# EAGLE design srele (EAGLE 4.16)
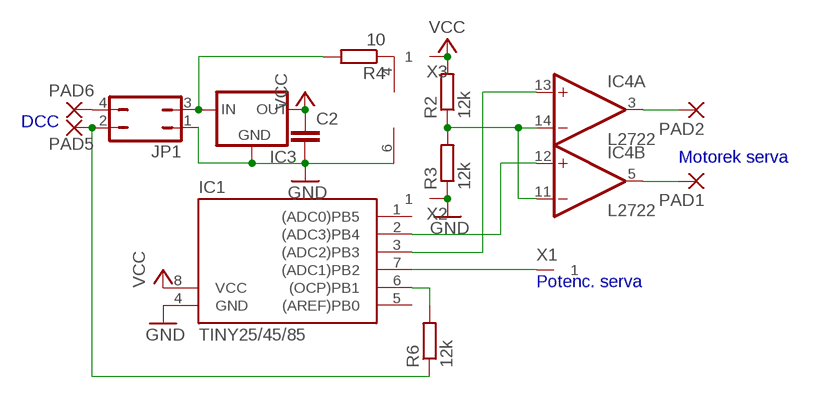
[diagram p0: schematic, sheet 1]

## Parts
C2  C-EU025-024X044  [C025-024X044]
IC1  TINY25/45/85  TINY15LP  [DIL08]
IC3  78LXX  [78LXX]
IC4  L2722  [SO16]
JP1  JP2Q  [JP2Q]
PAD1  SMD5  [SMD5]
PAD2  SMD5  [SMD5]
PAD5  SMD2  [SMD2]
PAD6  SMD2  [SMD2]
R2  12k  R-EU_0204/5  [0204/5]
R3  12k  R-EU_0204/5  [0204/5]
R4  10  R-EU_0207/10  [0207/10]
R6  12k  R-EU_0204/5  [0204/5]
X1  PAD-Y-ASYM  [Y_LONG_ASYM]
X2  PAD-Y-ASYM  [Y_LONG_ASYM]
X3  PAD-Y-ASYM  [Y_LONG_ASYM]

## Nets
GND: C2.2 IC1.4(GND) IC3.GND IC4.6(P:GND) JP1.1 R3.1 X2.A1
N$1: IC4.11(B:-IN) IC4.14(A:-IN) R2.1 R3.2
N$2: IC1.3((ADC2)PB3) IC4.13(A:+IN)
N$3: IC1.6((OCP)PB1) R6.2
N$4: IC1.2((ADC3)PB4) IC4.12(B:+IN)
N$5: JP1.2 PAD5.1(P) R6.1
N$6: IC4.3(A:OUT) PAD2.1(P)
N$8: IC4.5(B:OUT) PAD1.1(P)
N$9: IC4.4(P:V+) R4.1
N$10: JP1.4 PAD6.1(P)
N$12: IC1.7((ADC1)PB2) X1.A1
N$16: IC3.IN JP1.3 R4.2
VCC: C2.1 IC1.8(VCC) IC3.OUT R2.2 X3.A1
Unconnected: IC1.1((ADC0)PB5) IC1.5((AREF)PB0)

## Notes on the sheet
- DCC
- Motorek serva
- Potenc. serva

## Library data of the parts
C2 = RCL:C-EU: CAPACITOR, European symbol
IC1 = atmel-1:TINY15L: MICROCONTROLLER 2.7 V 1 Kbytes FLASH 64 bytes EEPROM 4-channel 10 bit ADC
IC3 = v-reg:78LXX: VOLTAGE REGULATOR
IC4 = LINEAR:L2722: OP AMP
JP1 = JUMPER:JP2Q: JUMPER
PAD1 PAD2 = wirepad:SMD5: SMD PAD
PAD5 PAD6 = wirepad:SMD2: SMD PAD
R2-R4 R6 = RCL:R-EU_: RESISTOR, European symbol
X1-X3 = special-pad:PAD-Y-ASYM: Y Long asymetrical Pad

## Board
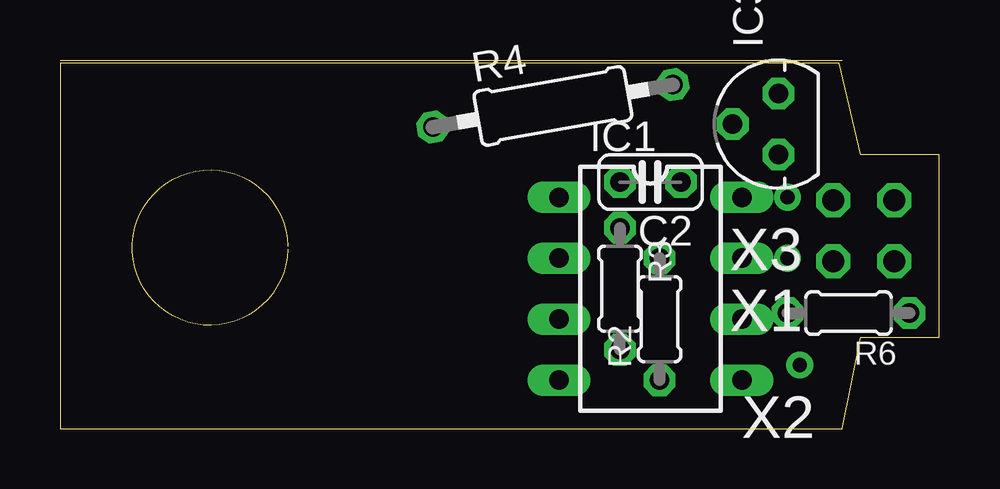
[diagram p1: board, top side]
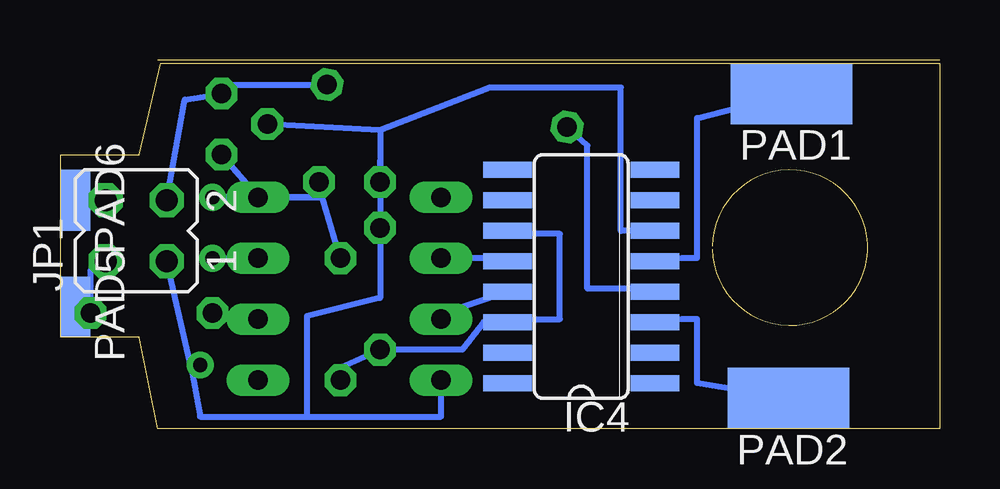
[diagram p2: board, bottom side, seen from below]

Size 36.63 x 15.37 mm. Coordinates in mm from the lower left corner, seen from the top.
Outline: 9.49,7.49 arc-358 9.49,7.62
Outline: 0,15.37 32.6,15.37
Outline: 36.63,11.42 33.36,11.42 32.47,15.24 0,15.23 0,0.01 32.6,0 33.36,3.82 36.63,3.82 36.63,11.42
Copper layers (1*16): Top 0.035mm / dielectric 1.5mm / Bottom 0.035mm
Design rules "default": minimum track width 10mil, minimum drill 24mil, track to track 8mil, track to pad 8mil, pad to pad 8mil, via to via 8mil, smd to smd 8mil, copper to edge 40mil, drill to drill 8mil, minimum pad ring 10mil, minimum via ring 8mil, stop-mask expansion 4mil, vias tented up to drill 0mil, thermal gap 10mil

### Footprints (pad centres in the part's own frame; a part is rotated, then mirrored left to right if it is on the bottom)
C025-024X044 = drill 0.813 octagon: 1 -1.27,0; 2 1.27,0
DIL08 = drill 0.813 long: 1 -3.81,-3.81; 2 -1.27,-3.81; 3 1.27,-3.81; 4 3.81,-3.81; 5 3.81,3.81; 6 1.27,3.81; 7 -1.27,3.81; 8 -3.81,3.81
78LXX = drill 0.813 octagon: GND 0,1.905; IN 1.27,0; OUT -1.27,0
SO16 = smd 0.66 x 2.032: 1 -4.445,-3.073; 2 -3.175,-3.073; 3 -1.905,-3.073; 4 -0.635,-3.073; 5 0.635,-3.073; 6 1.905,-3.073; 7 3.175,-3.073; 8 4.445,-3.073; 9 4.445,3.073; 10 3.175,3.073; 11 1.905,3.073; 12 0.635,3.073; 13 -0.635,3.073; 14 -1.905,3.073; 15 -3.175,3.073; 16 -4.445,3.073
JP2Q = drill 0.914 octagon: 1 -1.27,-1.27; 2 -1.27,1.27; 3 1.27,-1.27; 4 1.27,1.27
SMD5 = smd 2.54 x 5.08: 1 0,0
SMD2 = smd 1.27 x 2.54: 1 0,0
0204/5 = drill 0.813 octagon: 1 -2.54,0; 2 2.54,0
0207/10 = drill 0.813 octagon: 1 -5.08,0; 2 5.08,0
Y_LONG_ASYM = drill 0.6 round: A1 0,0

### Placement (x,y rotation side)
C2  24.6,10.29 180 top
IC1  24.6,5.84 270 top
IC3  29.93,12.7 90 top
IC4  14.95,6.35 90 bottom
JP1  33.49,8.25 90 bottom
PAD1  6.18,13.97 90 bottom
PAD2  6.31,1.27 90 bottom
PAD5  36.03,5.08 180 bottom
PAD6  36.03,9.52 180 bottom
R2  24.98,4.57 90 top
R3  23.33,5.84 270 top
R4  20.54,13.46 10 top
R6  32.86,4.83 180 top
X1  30.32,7.11 180 top
X2  30.82,2.67 180 top
X3  30.32,9.65 180 top

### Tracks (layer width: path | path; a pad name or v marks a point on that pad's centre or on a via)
GND
  Bottom 0.254: C2.2 R3.1 23.33,5.46 26.38,4.7 26.38,0.51 | 31.2,2.54 JP1.1 | 23.33,12.45 IC3.GND | C2.2 23.33,11.18 | X2.A1 31.2,2.54 | 31.2,2.54 30.82,0.51 26.38,0.51 | IC1.4 20.79,0.51 26.38,0.51 | 11.39,8.38 11.27,8.13 IC4.6 13.3,8.25 13.3,14.22 18.76,14.22 23.33,12.45 | 23.33,12.45 C2.2
N$1
  Bottom 0.254: IC4.11 16.85,8.13 15.84,8.13 15.84,4.57 16.85,4.57 IC4.14 19.01,4.45 19.9,3.3 R3.2 24.98,2.54 R2.1
N$2
  Bottom 0.254: IC4.13 18.38,5.59 19.9,5.08 IC1.3
N$3
  Bottom 0.254: R6.2 IC1.6
N$4
  Bottom 0.254: IC4.12 18.38,7.11 IC1.2
N$5
  Bottom 0.254: JP1.2 35.4,6.6 R6.1 PAD5.1
N$6
  Bottom 0.254: IC4.3 10.76,4.57 10.12,4.57 10.12,1.91 PAD2.1
N$8
  Bottom 0.254: IC4.5 10.76,7.11 10.12,7.11 10.12,12.95 PAD1.1
N$9
  Bottom 0.254: R4.1 14.69,11.81 14.69,5.84 11.39,5.84 | 11.39,5.84 11.39,5.71 | IC4.4 11.27,5.59 11.39,5.84
N$10
  Bottom 0.254: JP1.4 PAD6.1
N$12
  Bottom 0.254: X1.A1 IC1.7
N$16
  Bottom 0.254: R4.2 25.49,14.38 25.62,14.35 29.81,14.35 IC3.IN 31.46,13.72 JP1.3
VCC
  Bottom 0.254: IC1.8 IC3.OUT | X3.A1 IC1.8 | IC1.8 25.74,9.65 R2.2 | IC1.8 X3.A1 | X3.A1 25.87,9.65 C2.1

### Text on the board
bTest: @Zdeno | 1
